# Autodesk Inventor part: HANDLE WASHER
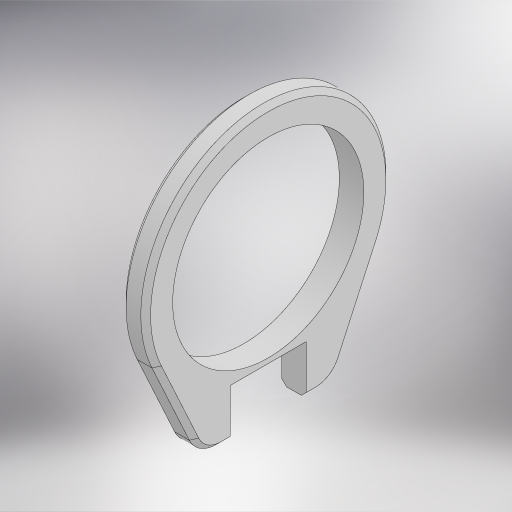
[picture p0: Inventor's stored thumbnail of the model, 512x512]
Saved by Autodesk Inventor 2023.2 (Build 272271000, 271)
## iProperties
Created: 2022-12
Part Number: HANDLE WASHER
Material: Generic
Document SubType Name: Modeling
Designer: AR
Mass: 4.31033 g
Surface Area: 31.6279 cm^2
Volume: 4.31033 cm^3
Density: 1 g/cm^3
Appearance: Default
Author: AR
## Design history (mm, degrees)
derived "_2 SPOOL CORD WRAP MP.ipt"
feature "HANDLE WASHER::_2 SPOOL CORD WRAP MP.ipt" dims "d0" = 10
tag "TaggingFeature1"
node "HANDLE WASHER"
